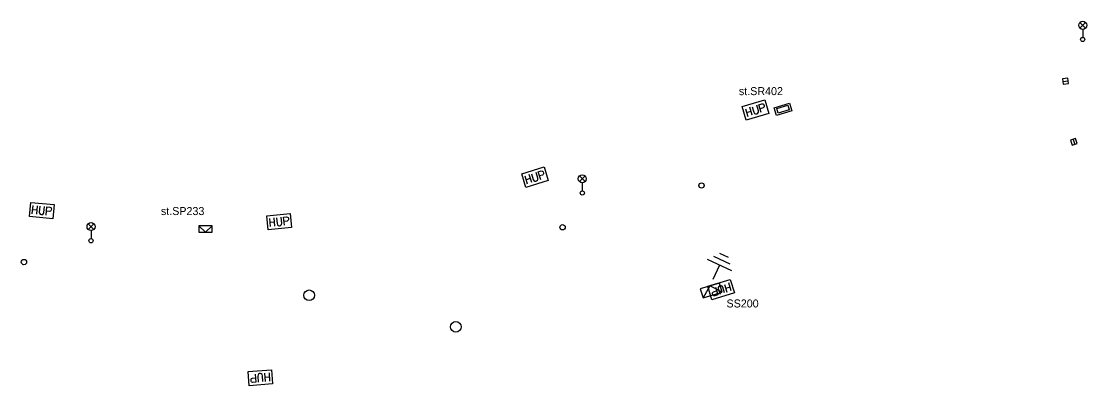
# Model space of a CAD drawing. Extents: x -762500 to -761250, y -1152983 to -1152297.
# Drawn here: x -761478.2 to -761378.3, y -1152361.3 to -1152327.2 of the extents above; entities that cross this region are included whole.
import ezdxf

# ---------------------------------------------------------------- set-up
doc = ezdxf.new("R2010")
doc.units = 0
for name, color, linetype in [('Vrstva 1', 7, 'Continuous'), ('Vrstva 2', 7, 'Continuous'), ('Vrstva 9', 7, 'Continuous')]:
    doc.layers.add(name, color=color, linetype=linetype)

msp = doc.modelspace()

# ---------------------------------------------------------------- linework, layer by layer
at = {"layer": 'Vrstva 1'}
for p, q in [((-761411.899, -1152349.343), (-761412.713, -1152348.959)), ((-761411.602, -1152350.589), (-761413.863, -1152349.522)), ((-761412.732, -1152350.056), (-761413.373, -1152351.412)), ((-761411.75, -1152349.966), (-761413.288, -1152349.241))]:
    msp.add_line(p, q, dxfattribs=at)
for points in [[(-761407.622, -1152335.314), (-761406.184, -1152334.888), (-761405.971, -1152335.607), (-761407.409, -1152336.033)], [(-761407.388, -1152335.401), (-761406.333, -1152335.088), (-761406.205, -1152335.52), (-761407.26, -1152335.832)], [(-761461.515, -1152346.98), (-761460.265, -1152346.98), (-761460.265, -1152346.38), (-761461.515, -1152346.38)], [(-761412.751, -1152351.733), (-761414.549, -1152352.267), (-761414.292, -1152353.13), (-761412.495, -1152352.595)]]:
    msp.add_lwpolyline(points, close=True, dxfattribs=at)
for points in [[(-761461.515, -1152346.38), (-761460.89, -1152346.98), (-761460.265, -1152346.38)], [(-761412.495, -1152352.595), (-761413.65, -1152352), (-761414.292, -1152353.13)]]:
    msp.add_lwpolyline(points, dxfattribs=at)
at = {"layer": 'Vrstva 9'}
for p, q in [((-761378.984, -1152327.868), (-761378.456, -1152327.34)), ((-761378.448, -1152327.865), (-761378.976, -1152327.336)), ((-761378.72, -1152327.98), (-761378.72, -1152328.73)), ((-761380.588, -1152332.87), (-761380.092, -1152332.81)), ((-761379.619, -1152338.283), (-761379.461, -1152338.757)), ((-761425.864, -1152342.238), (-761425.336, -1152341.71)), ((-761425.328, -1152342.235), (-761425.856, -1152341.706)), ((-761425.6, -1152342.35), (-761425.6, -1152343.1)), ((-761471.894, -1152346.708), (-761471.366, -1152346.18)), ((-761471.358, -1152346.705), (-761471.886, -1152346.176)), ((-761471.63, -1152346.82), (-761471.63, -1152347.57))]:
    msp.add_line(p, q, dxfattribs=at)
for points in [[(-761380.558, -1152333.119), (-761380.061, -1152333.059), (-761380.121, -1152332.561), (-761380.618, -1152332.621)], [(-761379.857, -1152338.363), (-761379.699, -1152338.837), (-761379.223, -1152338.678), (-761379.382, -1152338.203)]]:
    msp.add_lwpolyline(points, close=True, dxfattribs=at)
for points in [[(-761410.61, -1152335.207), (-761408.5, -1152334.582), (-761408.125, -1152335.847), (-761410.235, -1152336.473), (-761410.61, -1152335.207)], [(-761409.688, -1152335.221), (-761409.531, -1152335.75), (-761409.471, -1152335.845), (-761409.385, -1152335.895), (-761409.285, -1152335.904), (-761409.225, -1152335.886), (-761409.146, -1152335.824), (-761409.106, -1152335.737), (-761409.107, -1152335.624), (-761409.264, -1152335.095)], [(-761409.055, -1152335.033), (-761408.781, -1152334.952), (-761408.682, -1152334.961), (-761408.64, -1152334.986), (-761408.59, -1152335.047), (-761408.559, -1152335.152), (-761408.568, -1152335.231), (-761408.589, -1152335.274), (-761408.667, -1152335.335), (-761408.941, -1152335.417)], [(-761408.836, -1152335.771), (-761409.055, -1152335.033)], [(-761410.321, -1152335.408), (-761410.102, -1152336.146)], [(-761410.217, -1152335.756), (-761409.794, -1152335.631)], [(-761409.678, -1152336.021), (-761409.897, -1152335.282)], [(-761431.28, -1152341.512), (-761429.177, -1152340.865), (-761428.789, -1152342.126), (-761430.891, -1152342.774), (-761431.28, -1152341.512)], [(-761430.989, -1152341.71), (-761430.762, -1152342.446)], [(-761430.882, -1152342.057), (-761430.459, -1152341.927)], [(-761430.34, -1152342.316), (-761430.566, -1152341.58)], [(-761430.358, -1152341.516), (-761430.195, -1152342.044), (-761430.134, -1152342.138), (-761430.048, -1152342.187), (-761429.948, -1152342.195), (-761429.888, -1152342.177), (-761429.81, -1152342.114), (-761429.771, -1152342.026), (-761429.773, -1152341.913), (-761429.936, -1152341.386)], [(-761429.727, -1152341.322), (-761429.454, -1152341.238), (-761429.355, -1152341.246), (-761429.313, -1152341.271), (-761429.262, -1152341.33), (-761429.23, -1152341.435), (-761429.238, -1152341.514), (-761429.259, -1152341.557), (-761429.336, -1152341.62), (-761429.609, -1152341.704)], [(-761429.5, -1152342.058), (-761429.727, -1152341.322)], [(-761477.277, -1152344.18), (-761475.087, -1152344.393), (-761475.215, -1152345.707), (-761477.405, -1152345.493), (-761477.277, -1152344.18)], [(-761477.085, -1152344.475), (-761477.159, -1152345.241)], [(-761477.12, -1152344.836), (-761476.68, -1152344.879)], [(-761476.719, -1152345.284), (-761476.645, -1152344.517)], [(-761476.428, -1152344.539), (-761476.481, -1152345.088), (-761476.461, -1152345.198), (-761476.4, -1152345.278), (-761476.311, -1152345.324), (-761476.249, -1152345.33), (-761476.152, -1152345.302), (-761476.083, -1152345.235), (-761476.041, -1152345.131), (-761475.988, -1152344.581)], [(-761475.845, -1152345.369), (-761475.771, -1152344.603)], [(-761475.771, -1152344.603), (-761475.486, -1152344.63), (-761475.398, -1152344.676), (-761475.369, -1152344.715), (-761475.345, -1152344.79), (-761475.356, -1152344.899), (-761475.394, -1152344.969), (-761475.43, -1152345), (-761475.525, -1152345.028), (-761475.81, -1152345.001)], [(-761455.148, -1152345.428), (-761452.957, -1152345.224), (-761452.835, -1152346.538), (-761455.025, -1152346.742), (-761455.148, -1152345.428)], [(-761454.903, -1152345.681), (-761454.832, -1152346.448)], [(-761454.87, -1152346.043), (-761454.429, -1152346.002)], [(-761454.392, -1152346.407), (-761454.463, -1152345.64)], [(-761454.246, -1152345.62), (-761454.195, -1152346.17), (-761454.154, -1152346.274), (-761454.079, -1152346.341), (-761453.983, -1152346.369), (-761453.921, -1152346.363), (-761453.832, -1152346.317), (-761453.776, -1152346.239), (-761453.755, -1152346.129), (-761453.806, -1152345.579)], [(-761453.589, -1152345.559), (-761453.304, -1152345.532), (-761453.209, -1152345.56), (-761453.173, -1152345.593), (-761453.135, -1152345.662), (-761453.125, -1152345.772), (-761453.149, -1152345.847), (-761453.179, -1152345.885), (-761453.267, -1152345.93), (-761453.552, -1152345.957)], [(-761453.517, -1152346.325), (-761453.589, -1152345.559)], [(-761411.355, -1152352.665), (-761413.46, -1152353.302), (-761413.843, -1152352.039), (-761411.737, -1152351.401), (-761411.355, -1152352.665)], [(-761413.131, -1152352.111), (-761412.908, -1152352.848)], [(-761412.277, -1152352.656), (-761412.437, -1152352.128), (-761412.498, -1152352.034), (-761412.584, -1152351.984), (-761412.684, -1152351.975), (-761412.744, -1152351.993), (-761412.822, -1152352.056), (-761412.861, -1152352.144), (-761412.86, -1152352.256), (-761412.7, -1152352.784)], [(-761412.291, -1152351.856), (-761412.068, -1152352.593)], [(-761411.75, -1152352.118), (-761412.173, -1152352.246)], [(-761411.645, -1152352.465), (-761411.868, -1152351.728)], [(-761412.908, -1152352.848), (-761413.182, -1152352.931), (-761413.281, -1152352.922), (-761413.323, -1152352.897), (-761413.373, -1152352.837), (-761413.405, -1152352.732), (-761413.397, -1152352.653), (-761413.375, -1152352.61), (-761413.298, -1152352.548), (-761413.024, -1152352.465)], [(-761454.62, -1152361.17), (-761456.813, -1152361.342), (-761456.917, -1152360.026), (-761454.723, -1152359.854), (-761454.62, -1152361.17)], [(-761455.362, -1152360.18), (-761455.301, -1152360.947)], [(-761454.861, -1152360.913), (-761454.921, -1152360.145)], [(-761456.177, -1152361.016), (-761456.462, -1152361.039), (-761456.556, -1152361.009), (-761456.592, -1152360.976), (-761456.629, -1152360.906), (-761456.637, -1152360.797), (-761456.612, -1152360.722), (-761456.582, -1152360.684), (-761456.493, -1152360.64), (-761456.208, -1152360.618)], [(-761456.237, -1152360.249), (-761456.177, -1152361.016)], [(-761455.519, -1152360.965), (-761455.562, -1152360.414), (-761455.601, -1152360.309), (-761455.675, -1152360.242), (-761455.77, -1152360.212), (-761455.833, -1152360.217), (-761455.923, -1152360.261), (-761455.98, -1152360.339), (-761456.003, -1152360.449), (-761455.959, -1152360.999)], [(-761454.889, -1152360.551), (-761455.33, -1152360.586)]]:
    msp.add_lwpolyline(points, dxfattribs=at)
for centre, radius in [((-761378.72, -1152327.605), 0.375), ((-761378.72, -1152328.93), 0.2), ((-761425.6, -1152341.975), 0.375), ((-761425.6, -1152343.3), 0.2), ((-761414.43, -1152342.6), 0.25), ((-761471.63, -1152346.445), 0.375), ((-761427.45, -1152346.51), 0.25), ((-761471.63, -1152347.77), 0.2), ((-761477.91, -1152349.77), 0.25), ((-761451.19, -1152352.88), 0.5), ((-761437.45, -1152355.83), 0.5)]:
    msp.add_circle(centre, radius, dxfattribs=at)

# ---------------------------------------------------------------- texts
at = {"layer": 'Vrstva 2'}
for s, p in [('st.SR402', (-761410.93, -1152334.14)), ('st.SP233', (-761465.08, -1152345.37)), ('SS200', (-761412.09, -1152354.02))]:
    msp.add_text(s, height=0.75, dxfattribs=at).set_placement(p)

doc.saveas('drawing.dxf')
